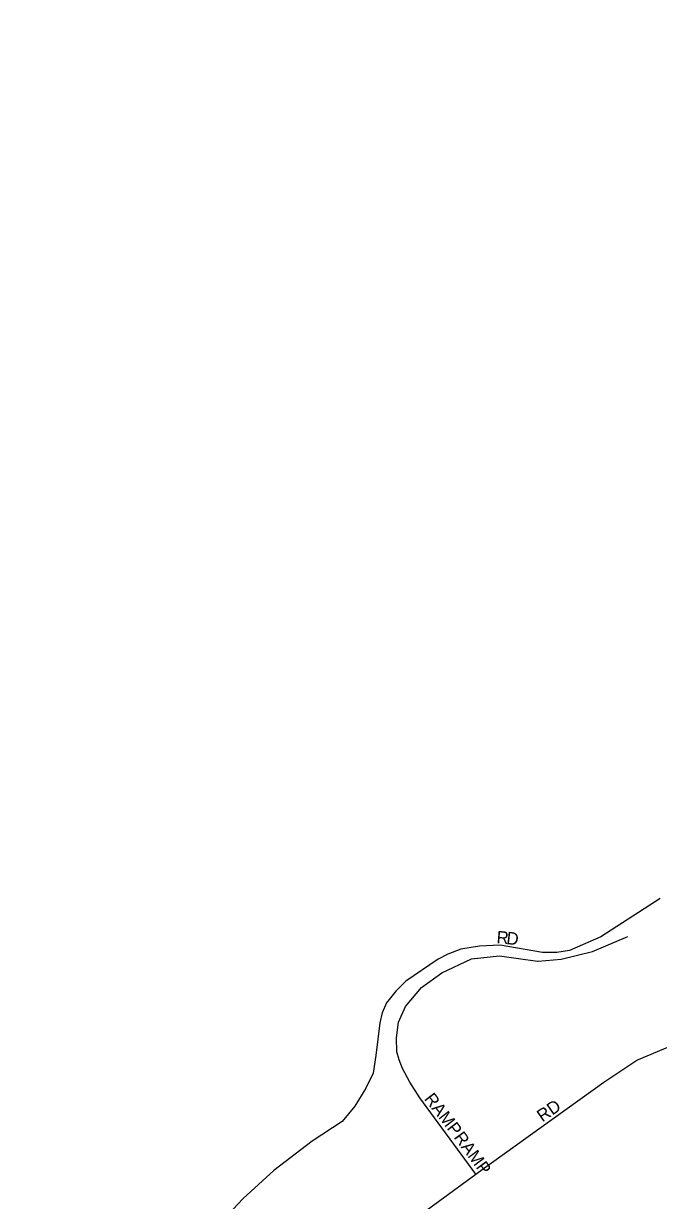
# Model space of a CAD drawing. Extents: x 0 to 96.2, y -27.5 to 31.3.
# Drawn here: x 5.192 to 5.674, y 20.006 to 20.9 of the extents above; entities that cross this region are included whole.
import ezdxf

# ---------------------------------------------------------------- set-up
doc = ezdxf.new("R2010")
doc.units = 0
doc.layers.add('TB_PP_20x10_GRID', color=7, linetype='Continuous')
doc.layers.add('TB_PP_30x10', color=7, linetype='Continuous')

msp = doc.modelspace()

# ---------------------------------------------------------------- linework, layer by layer
at = {"layer": 'TB_PP_20x10_GRID'}
for points in [[(5.53532, 20.02613), (5.53729, 20.02771), (5.58506, 20.06171), (5.63258, 20.09606), (5.65773, 20.11263), (5.68594, 20.12459), (5.74156, 20.14275), (5.75776, 20.14869), (5.76696, 20.15299), (5.77616, 20.1573), (5.80147, 20.17225), (5.85856, 20.21319), (5.90814, 20.25188), (5.93194, 20.27889), (5.98582, 20.35125), (6.03034, 20.41169), (6.05381, 20.43847), (6.07133, 20.45699), (6.12572, 20.49665), (6.40933, 20.6956), (6.44985, 20.72697), (6.50094, 20.76988), (6.54195, 20.80174), (6.68146, 20.9)], [(5.67522, 20.23552), (5.63038, 20.20626), (5.60649, 20.19602), (5.59686, 20.19455), (5.58602, 20.19456), (5.55385, 20.19992), (5.53807, 20.19937), (5.52393, 20.19704), (5.51413, 20.1933), (5.50666, 20.18941), (5.4822, 20.17262), (5.47463, 20.16499), (5.46755, 20.15636), (5.46421, 20.14866), (5.46234, 20.14104), (5.45947, 20.11623), (5.45728, 20.10285), (5.45169, 20.09133), (5.44329, 20.07765), (5.43365, 20.06614), (5.41094, 20.0512), (5.38194, 20.02884), (5.3586, 20.00775), (5.28195, 19.92581)], [(5.58269, 20.18793), (5.60019, 20.18933), (5.62384, 20.19528), (5.65071, 20.20669)], [(5.53532, 20.02613), (5.49288, 20.08409), (5.48512, 20.09601), (5.47952, 20.10648), (5.47696, 20.11298), (5.47527, 20.11914), (5.47512, 20.12954), (5.47647, 20.14152), (5.48193, 20.15358), (5.49413, 20.16788), (5.50955, 20.17897), (5.53199, 20.18977), (5.55317, 20.19197), (5.58208, 20.18788), (5.58269, 20.18793)], [(5.19174, 19.74335), (5.2285, 19.76964), (5.26161, 19.79421), (5.27285, 19.80314), (5.2992, 19.82798), (5.34488, 19.87682), (5.36765, 19.90262), (5.37685, 19.91102), (5.43493, 19.95373), (5.4909, 19.9938), (5.53532, 20.02613)]]:
    msp.add_lwpolyline(points, dxfattribs=at)

# ---------------------------------------------------------------- texts
at = {"layer": 'TB_PP_30x10'}
for s, rotation, p in [('R', 355.551, (5.55081, 20.20149)), ('D', 353.47151, (5.5582, 20.20092)), ('RAMP', 307.74738, (5.49565, 20.08322)), ('RD', 34.50504, (5.58583, 20.06534)), ('RAMP', 306.56981, (5.51818, 20.05403))]:
    msp.add_text(s, height=0.00947, rotation=rotation, dxfattribs=at).set_placement(p)

doc.saveas('drawing.dxf')
